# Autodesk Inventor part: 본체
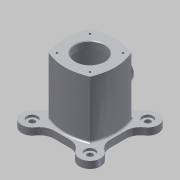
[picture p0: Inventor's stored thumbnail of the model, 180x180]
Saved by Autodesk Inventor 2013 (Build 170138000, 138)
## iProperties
Created: 2016-05
Part Number: 본체
Material: 알루미늄 6061
Document SubType Name: Modeling
Designer: Administrator
Density: 2.71 g/cm^3
Mass: 1093.96 g
Surface Area: 874.795 cm^2
Volume: 403.674 cm^3
Author: Administrator
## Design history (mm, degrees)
sketch "스케치1" dims "d2" = 100
  geometry: L1 (0, 0)-(68.866, 0); L2 (0, 0)-(46.209, 46.209); L3 (0, 0)-(0, 55.666); L4 (0, 0)-(-64.598, 0); A1 r 43 centre (0, 0) between (43, 0) and (0, 43); A2 r 97.722 centre (-54.687, -2.618) between (43, 0) and (35.355, 35.355); A3 r 96.975 centre (-2.457, -53.944) between (35.355, 35.355) and (0, 43); A4 r 96.975 centre (2.457, -53.944) between (0, 43) and (-35.355, 35.355); A5 r 97.722 centre (54.687, -2.618) between (-35.355, 35.355) and (-43, 0); A6 r 97.722 centre (54.687, 2.618) between (-43, 0) and (-35.355, -35.355); A7 r 96.975 centre (2.457, 53.944) between (-35.355, -35.355) and (0, -43); A8 r 96.975 centre (-2.457, 53.944) between (0, -43) and (35.355, -35.355); A9 r 97.722 centre (-54.687, 2.618) between (35.355, -35.355) and (43, 0); 1 further point
  constraints: 18 point on circle, 11 symmetric about line, 9 centre point, 8 end point, 3 point on line, 2 coincident, 2 perpendicular, 1 horizontal, 9 other
  dimensions: "d0" = 86 diameter of A1; "d3" = 45 deg angle of L2 L1; "d4" = 96.97525 radius of A3; "d5" = 97.72166 radius of A2
extrude "돌출1" new body sketch "스케치1" stored distance "d6" = 110; taper "d7" = 0 deg
sketch "스케치2"
  geometry: C1 r 35 at (0, 0); 1 further point
  constraints: 1 centre point, 1 coincident
  dimensions: "d8" = 70 diameter of C1
extrude "돌출2" cut sketch "스케치2" stored distance "d10" = 86; taper "d11" = 0 deg
sketch "스케치3"
  geometry: L1 (48, 13.489)-(48, -13.489); L2 (13.489, -48)-(-13.489, -48); L3 (-48, -13.489)-(-48, 13.489); L4 (0, 0)-(173.331, 0); L5 (0, 0)-(84.416, 84.416); L6 (-13.489, 48)-(13.489, 48); L7 (0, 0)-(0, 62.453); L8 (-13.489, -48)-(13.489, -48); A1 r 97.722 centre (54.687, -2.618) between (-35.355, 35.355) and (-43, 0) reference; A2 r 97.722 centre (54.687, 2.618) between (-43, 0) and (-35.355, -35.355) reference; A3 r 96.975 centre (2.457, 53.944) between (-35.355, -35.355) and (0, -43) reference; A4 r 96.975 centre (-2.457, 53.944) between (0, -43) and (35.355, -35.355) reference; A5 r 97.722 centre (-54.687, 2.618) between (35.355, -35.355) and (43, 0) reference; A6 r 97.722 centre (-54.687, -2.618) between (43, 0) and (35.355, 35.355) reference; A7 r 96.975 centre (-2.457, -53.944) between (35.355, 35.355) and (0, 43) reference; A8 r 96.975 centre (2.457, -53.944) between (0, 43) and (-35.355, 35.355) reference; A9 r 70 centre (0, 0) between (49.497, 49.497) and (60.531, 35.157); A10 r 18 centre (49.497, 49.497) between (59.336, 34.424) and (34.424, 59.336); A11 r 25 centre (13.489, 73) between (13.489, 48) and (34.424, 59.336); A12 r 25 centre (73, 13.489) between (59.336, 34.424) and (48, 13.489); A13 r 18 centre (-49.497, 49.497) between (-34.424, 59.336) and (-59.336, 34.424); A14 r 25 centre (-13.489, 73) between (-34.424, 59.336) and (-13.489, 48); A15 r 25 centre (-73, 13.489) between (-48, 13.489) and (-59.336, 34.424); A16 r 25 centre (-73, -13.489) between (-59.336, -34.424) and (-48, -13.489); A17 r 18 centre (-49.497, -49.497) between (-59.336, -34.424) and (-34.424, -59.336); A18 r 25 centre (-13.489, -73) between (-13.489, -48) and (-34.424, -59.336); A19 r 25 centre (13.489, -73) between (34.424, -59.336) and (13.489, -48); A20 r 18 centre (49.497, -49.497) between (34.424, -59.336) and (59.336, -34.424); A21 r 25 centre (73, -13.489) between (48, -13.489) and (59.336, -34.424); A22 r 97.722 centre (-54.687, -2.618) between (43, 0) and (35.355, 35.355); A23 r 96.975 centre (-2.457, 53.944) between (0, -43) and (35.355, -35.355); A24 r 96.975 centre (2.457, 53.944) between (-35.355, -35.355) and (0, -43); A25 r 97.722 centre (54.687, 2.618) between (-43, 0) and (-35.355, -35.355); A26 r 97.722 centre (54.687, -2.618) between (-35.355, 35.355) and (-43, 0); A27 r 96.975 centre (2.457, -53.944) between (0, 43) and (-35.355, 35.355); A28 r 96.975 centre (-2.457, -53.944) between (35.355, 35.355) and (0, 43); A29 r 97.722 centre (-54.687, 2.618) between (35.355, -35.355) and (43, 0); 8 further points
  constraints: 44 point on circle, 27 symmetric about line, 21 centre point, 16 end point, 8 concentric, 5 tangent, 2 perpendicular, 2 point on line, 1 coincident, 1 horizontal, 1 parallel, 9 other
  dimensions: "d15" = 48 distance from line of point (0, 0) L3 (= 0.5 x d12); "d17" = 140 diameter of A9; "d18" = 45 deg angle of L4 L5; "d19" = 36 diameter of A10; "d21" = 50 diameter of A11; "d22" = 50 diameter of A12; "d23" = 96 distance between parallel lines of L1 L3; "d24" = 48 distance from line of L6 point (0, 0); "d108" = 18 radius of A13 (derived)
extrude "돌출3" join sketch "스케치3" distance "d25" = 12; taper "d26" = 0 deg
sketch "스케치4"
  geometry: C1 r 5 at (-49.497, 49.497); C2 r 5 at (49.497, 49.497); C3 r 5 at (49.497, -49.497); C4 r 5 at (-49.497, -49.497); A1 r 18 centre (49.497, 49.497) between (59.336, 34.424) and (34.424, 59.336) reference; A2 r 18 centre (-49.497, 49.497) between (-34.424, 59.336) and (-59.336, 34.424) reference; A3 r 18 centre (-49.497, -49.497) between (-59.336, -34.424) and (-34.424, -59.336) reference; A4 r 18 centre (49.497, -49.497) between (34.424, -59.336) and (59.336, -34.424) reference; 1 further point
  constraints: 4 centre point, 4 coincident, 3 equal radius
  dimensions: "d27" = 10 diameter of C1
extrude "돌출4" cut sketch "스케치4" distance "d29" = 12; taper "d30" = 0 deg
sketch "스케치5"
  geometry: C1 r 5 at (49.497, -49.497) reference; C2 r 5 at (-49.497, 49.497) reference; C3 r 5 at (49.497, 49.497) reference; C4 r 5 at (-49.497, -49.497) reference; C5 r 9 at (-49.497, 49.497); C6 r 9 at (49.497, 49.497); C7 r 9 at (49.497, -49.497); C8 r 9 at (-49.497, -49.497); A1 r 18 centre (49.497, 49.497) between (59.336, 34.424) and (34.424, 59.336) reference; A2 r 18 centre (-49.497, 49.497) between (-34.424, 59.336) and (-59.336, 34.424) reference; A3 r 18 centre (-49.497, -49.497) between (-59.336, -34.424) and (-34.424, -59.336) reference; A4 r 18 centre (49.497, -49.497) between (34.424, -59.336) and (59.336, -34.424) reference; 1 further point
  constraints: 4 centre point, 4 coincident, 3 equal radius
  dimensions: "d31" = 18 diameter of C5
extrude "돌출5" cut sketch "스케치5" distance "d33" = 4; taper "d34" = 0 deg
sketch "스케치6"
  geometry: C1 r 25 at (0, 0); 1 further point
  constraints: 1 centre point, 1 coincident
  dimensions: "d35" = 50 diameter of C1
extrude "돌출6" cut sketch "스케치6" distance "d37" = 12; taper "d38" = 0 deg
fillet "모깎기1" dims "d39" = 3
node "작업 평면1"
chamfer "모따기1" distance "d53" = 1; stored, may be unused: second distance "d54" = 2, angle "d55" = 45 deg
sketch "스케치10" dims "d56" = 80
  geometry: L1 (0, 0)-(96.45, 0); L2 (0, 0)-(32.969, 32.969); C1 r 26 at (0, 0) reference; 1 further point
  constraints: 4 end point, 1 coincident, 1 horizontal, 1 point on line, 3 other
  dimensions: "d59" = 45 deg angle of L1 L2
hole "구멍1" sketch "스케치10" at (28.284, 28.284) diameter "d61" = 3.242; stored, may be unused: countersink angle "d65" = 90 deg, drill point angle "d67" = 118 deg; dims "d62" = 7, "d63" = 4, "d64" = 2, "d66" = 10
node "작업 평면2"
sketch "스케치11"
  geometry: L1 (0, 55)-(-35.355, 55) reference; 2 further points
  constraints: 1 other
  dimensions: "d72" = 49 distance from line of point (-29, 6) L1; "d73" = 29 horizontal distance of point (-29, 6) point (0, 0)
feature "엠보싱1" sketch "스케치11" dims "d0" = 86, "d2" = 100, "d3" = 45 deg, "d4" = 96.97525, "d5" = 97.72166, "d10" = 86, "d74" = 1, "d75" = 0
node "작업 평면3"
sketch "스케치15"
  geometry: L1 (0, 55)-(-35.355, 55) reference; L2 (0, -40)-(0, 55) reference; C1 r 20 at (0, 6); 1 further point
  constraints: 1 centre point, 1 point on line
  dimensions: "d90" = 40 diameter of C1; "d93" = 49 distance from line of L1 C1.centre
extrude "돌출10" join sketch "스케치15" stored distance "d94" = 8; taper "d95" = 10 deg
fillet "모깎기2" dims "d96" = 3
sketch "스케치16"
  geometry: C1 r 20 at (0, 6) reference; C2 r 15 at (0, 6); 1 further point
  constraints: 1 centre point, 1 coincident
  dimensions: "d97" = 30 diameter of C2
extrude "돌출11" cut sketch "스케치16" distance "d99" = 8; taper "d100" = 0 deg
sketch "스케치17"
  geometry: C1 r 20 at (0, 6) reference; C2 r 12.5 at (0, 6); 1 further point
  constraints: 1 centre point, 1 coincident
  dimensions: "d101" = 25 diameter of C2
extrude "돌출12" cut sketch "스케치17" stored distance "d103" = 8; taper "d104" = 0 deg
chamfer "모따기2" distance "d105" = 1; stored, may be unused: second distance "d106" = 2, angle "d107" = 45 deg
node "솔리드1"
mirror "대칭1"
pattern_circular "원형 패턴1" dims angle "d69" = 360 deg
mirror "대칭2"
other parameters: "d12" = 96, "d40" = 55, "d89" = 55
